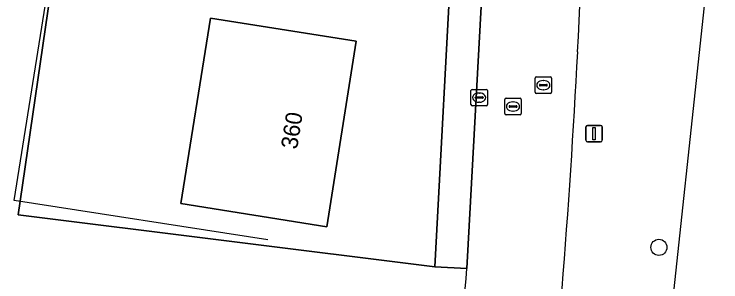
# Model space of a CAD drawing. Extents: x 154324 to 155744, y 382937 to 384188.
# Drawn here: x 155354.48 to 155397.41, y 383333.48 to 383349.73 of the extents above; entities that cross this region are included whole.
import ezdxf

# ---------------------------------------------------------------- set-up
doc = ezdxf.new("R2010")
doc.units = 0
for name, color, linetype in [('IMGEO_Berm_groen', 7, 'Continuous'), ('IMGEO_Boom', 7, 'Continuous'), ('IMGEO_Erf', 7, 'Continuous'), ('IMGEO_Groenvoorziening', 7, 'Continuous'), ('IMGEO_Hek', 7, 'Continuous'), ('IMGEO_Kolk', 7, 'Continuous'), ('IMGEO_Lichtmast', 7, 'Continuous'), ('IMGEO_Pand', 7, 'Continuous'), ('IMGEO_Pand_nummerreeks', 7, 'Continuous'), ('IMGEO_Rijbaan_lokaal_open', 7, 'Continuous'), ('IMGEO_Rioolput', 7, 'Continuous'), ('IMGEO_Voetpad_open', 7, 'Continuous')]:
    doc.layers.add(name, color=color, linetype=linetype)

msp = doc.modelspace()

# ---------------------------------------------------------------- linework, layer by layer
at = {"layer": 'IMGEO_Berm_groen'}
msp.add_lwpolyline([(155393.141, 383320.278), (155393.828, 383326.071), (155396.722, 383353.081), (155397.412, 383377.951), (155390.399, 383378.047), (155389.068, 383377.555)], dxfattribs=at)
for centre, radius, start, end in [((155026.251, 383366.771), 362.977, 356.94684, 1.70249), ((154889.758, 383373.172), 499.618, 353.74726, 357.04758)]:
    msp.add_arc(centre, radius, start, end, dxfattribs=at)
at = {"layer": 'IMGEO_Boom'}
msp.add_circle((155393.648, 383335.575), 0.489, dxfattribs=at)
at = {"layer": 'IMGEO_Erf'}
msp.add_lwpolyline([(155379.37, 383377.808), (155377.693, 383376.769), (155375.684, 383375.726), (155373.779, 383374.896), (155371.854, 383374.2), (155369.627, 383373.633), (155368.206, 383373.461), (155366.044, 383373.562), (155360.106, 383374.508), (155358.814, 383365.632), (155354.844, 383338.369), (155354.723, 383337.539), (155380.034, 383334.398), (155381.119, 383354.403)], dxfattribs=at)
msp.add_lwpolyline([(155366.404, 383349.488), (155375.255, 383348.08), (155373.484, 383336.828), (155364.602, 383338.245)], close=True, dxfattribs=at)
at = {"layer": 'IMGEO_Groenvoorziening'}
msp.add_lwpolyline([(155381.974, 383334.287), (155380.034, 383334.398), (155354.723, 383337.539), (155354.844, 383338.369), (155358.814, 383365.632)], dxfattribs=at)
msp.add_arc((155071.527, 383356.622), 311.25, 352.27674, 355.8849, dxfattribs=at)
at = {"layer": 'IMGEO_Hek'}
msp.add_lwpolyline([(155369.884, 383336.037), (155354.478, 383338.426), (155359.411, 383369.381)], dxfattribs=at)
at = {"layer": 'IMGEO_Kolk'}
for p, q in [((155382.231, 383344.237), (155382.231, 383345.089)), ((155382.306, 383345.163), (155383.158, 383345.163)), ((155382.719, 383344.943), (155382.744, 383344.943)), ((155383.232, 383345.089), (155383.232, 383344.237)), ((155382.49, 383344.657), (155382.49, 383344.669)), ((155382.928, 383344.62), (155382.53, 383344.62)), ((155382.533, 383344.706), (155382.931, 383344.706)), ((155382.974, 383344.669), (155382.974, 383344.657)), ((155383.158, 383344.163), (155382.306, 383344.163)), ((155382.742, 383344.383), (155382.717, 383344.383))]:
    msp.add_line(p, q, dxfattribs=at)
for points in [[(155382.231, 383344.237), (155382.231, 383345.089)], [(155382.306, 383345.163), (155383.158, 383345.163)], [(155383.232, 383345.089), (155383.232, 383344.237)], [(155383.158, 383344.163), (155382.306, 383344.163)]]:
    msp.add_lwpolyline(points, dxfattribs=at)
for centre, radius, start, end in [((155382.308, 383345.087), 0.0765, 91.552, 178.448), ((155382.308, 383345.087), 0.0765, 91.552, 178.448), ((155383.156, 383345.087), 0.0765, 1.552, 88.448), ((155383.156, 383345.087), 0.0765, 1.552, 88.448), ((155382.53, 383344.666), 0.0403, 85.8775, 175.7526), ((155382.527, 383344.656), 0.0366, 178.938, 274.7102), ((155382.931, 383344.663), 0.043, 264.8664, 352.4533), ((155382.935, 383344.668), 0.0386, 1.7309, 96.639), ((155382.308, 383344.239), 0.0765, 181.552, 268.448), ((155382.308, 383344.239), 0.0765, 181.552, 268.448), ((155383.156, 383344.239), 0.0765, 271.552, 358.448), ((155383.156, 383344.239), 0.0765, 271.552, 358.448)]:
    msp.add_arc(centre, radius, start, end, dxfattribs=at)
for centre, major_axis, ratio, start_param, end_param in [((155382.718, 383344.663), (-0.387, 0.002), 0.722429, 4.712389, 7.853982), ((155382.743, 383344.663), (-0.39, 0.002), 0.717154, 1.570796, 4.712389)]:
    msp.add_ellipse(centre, major_axis=major_axis, ratio=ratio, start_param=start_param, end_param=end_param, dxfattribs=at)
at = {"layer": 'IMGEO_Lichtmast'}
for p, q in [((155389.214, 383342.08), (155389.214, 383342.88)), ((155389.214, 383342.88), (155389.214, 383342.08)), ((155389.314, 383342.98), (155390.104, 383342.98)), ((155390.104, 383342.98), (155389.314, 383342.98)), ((155390.204, 383342.88), (155390.204, 383342.08)), ((155390.204, 383342.08), (155390.204, 383342.88)), ((155390.104, 383341.98), (155389.314, 383341.98)), ((155389.314, 383341.98), (155390.104, 383341.98))]:
    msp.add_line(p, q, dxfattribs=at)
msp.add_lwpolyline([(155389.634, 383342.855), (155389.784, 383342.855), (155389.784, 383342.105), (155389.634, 383342.105), (155389.634, 383342.855)], dxfattribs=at)
for centre, start, end in [((155389.314, 383342.88), 90, 180), ((155389.314, 383342.88), 90, 180), ((155390.104, 383342.88), 0, 90), ((155390.104, 383342.88), 360, 90), ((155389.314, 383342.08), 180, 270), ((155389.314, 383342.08), 180, 270), ((155390.104, 383342.08), 270, 0), ((155390.104, 383342.08), 270, 0)]:
    msp.add_arc(centre, 0.1, start, end, dxfattribs=at)
at = {"layer": 'IMGEO_Pand'}
msp.add_lwpolyline([(155375.255, 383348.08), (155366.404, 383349.488), (155364.602, 383338.245), (155373.484, 383336.828)], close=True, dxfattribs=at)
at = {"layer": 'IMGEO_Rijbaan_lokaal_open'}
msp.add_lwpolyline([(155379.61, 383421.518), (155379.69, 383421.052), (155380.297, 383417.532), (155380.555, 383416.035), (155380.615, 383415.683), (155382.189, 383397.912), (155383.12, 383377.352), (155383.264, 383374.318), (155383.19, 383366.215), (155383.081, 383354.275), (155381.974, 383334.287)], dxfattribs=at)
for centre, radius, start, end in [((155026.251, 383366.771), 362.977, 356.94684, 1.70249), ((154889.758, 383373.172), 499.618, 353.74726, 357.04758), ((155071.527, 383356.622), 311.25, 352.27674, 355.8849)]:
    msp.add_arc(centre, radius, start, end, dxfattribs=at)
at = {"layer": 'IMGEO_Rioolput'}
for p, q in [((155386.127, 383344.991), (155386.127, 383345.843)), ((155386.202, 383345.917), (155387.054, 383345.917)), ((155387.128, 383345.843), (155387.128, 383344.991)), ((155386.386, 383345.411), (155386.386, 383345.423)), ((155386.824, 383345.374), (155386.426, 383345.374)), ((155386.429, 383345.46), (155386.827, 383345.46)), ((155386.615, 383345.697), (155386.64, 383345.697)), ((155386.87, 383345.423), (155386.87, 383345.411)), ((155386.638, 383345.137), (155386.613, 383345.137)), ((155384.285, 383343.698), (155384.285, 383344.55)), ((155384.36, 383344.624), (155385.212, 383344.624)), ((155385.286, 383344.55), (155385.286, 383343.698)), ((155387.054, 383344.917), (155386.202, 383344.917)), ((155384.544, 383344.118), (155384.544, 383344.13)), ((155384.982, 383344.081), (155384.584, 383344.081)), ((155384.587, 383344.167), (155384.985, 383344.167)), ((155384.773, 383344.404), (155384.798, 383344.404)), ((155385.028, 383344.13), (155385.028, 383344.118)), ((155384.796, 383343.844), (155384.771, 383343.844)), ((155385.212, 383343.624), (155384.36, 383343.624))]:
    msp.add_line(p, q, dxfattribs=at)
for points in [[(155386.127, 383344.991), (155386.127, 383345.843)], [(155386.202, 383345.917), (155387.054, 383345.917)], [(155387.128, 383345.843), (155387.128, 383344.991)], [(155384.285, 383343.698), (155384.285, 383344.55)], [(155384.36, 383344.624), (155385.212, 383344.624)], [(155385.286, 383344.55), (155385.286, 383343.698)], [(155387.054, 383344.917), (155386.202, 383344.917)], [(155385.212, 383343.624), (155384.36, 383343.624)]]:
    msp.add_lwpolyline(points, dxfattribs=at)
for centre, radius, start, end in [((155386.204, 383345.841), 0.0765, 91.552, 178.448), ((155386.204, 383345.841), 0.0765, 91.552, 178.448), ((155387.052, 383345.841), 0.0765, 1.552, 88.448), ((155387.052, 383345.841), 0.0765, 1.552, 88.448), ((155386.426, 383345.42), 0.0403, 85.8775, 175.7526), ((155386.423, 383345.41), 0.0366, 178.938, 274.7102), ((155386.827, 383345.417), 0.043, 264.8664, 352.4533), ((155386.831, 383345.422), 0.0386, 1.7309, 96.639), ((155386.204, 383344.993), 0.0765, 181.552, 268.448), ((155386.204, 383344.993), 0.0765, 181.552, 268.448), ((155387.052, 383344.993), 0.0765, 271.552, 358.448), ((155387.052, 383344.993), 0.0765, 271.552, 358.448), ((155384.362, 383344.548), 0.0765, 91.552, 178.448), ((155384.362, 383344.548), 0.0765, 91.552, 178.448), ((155385.21, 383344.548), 0.0765, 1.552, 88.448), ((155385.21, 383344.548), 0.0765, 1.552, 88.448), ((155384.584, 383344.127), 0.0403, 85.8775, 175.7526), ((155384.581, 383344.117), 0.0366, 178.938, 274.7102), ((155384.985, 383344.124), 0.043, 264.8664, 352.4533), ((155384.989, 383344.129), 0.0386, 1.7309, 96.639), ((155384.362, 383343.7), 0.0765, 181.552, 268.448), ((155384.362, 383343.7), 0.0765, 181.552, 268.448), ((155385.21, 383343.7), 0.0765, 271.552, 358.448), ((155385.21, 383343.7), 0.0765, 271.552, 358.448)]:
    msp.add_arc(centre, radius, start, end, dxfattribs=at)
for centre, major_axis, ratio, start_param, end_param in [((155386.614, 383345.417), (-0.387, 0.002), 0.722429, 4.712389, 7.853982), ((155386.639, 383345.417), (-0.39, 0.002), 0.717154, 1.570796, 4.712389), ((155384.772, 383344.124), (-0.387, 0.002), 0.722429, 4.712389, 7.853982), ((155384.797, 383344.124), (-0.39, 0.002), 0.717154, 1.570796, 4.712389)]:
    msp.add_ellipse(centre, major_axis=major_axis, ratio=ratio, start_param=start_param, end_param=end_param, dxfattribs=at)
at = {"layer": 'IMGEO_Voetpad_open'}
msp.add_lwpolyline([(155381.184, 383376.925), (155381.295, 383374.612), (155381.119, 383354.403), (155380.034, 383334.398), (155381.974, 383334.287), (155383.081, 383354.275), (155383.19, 383366.215), (155383.264, 383374.318), (155383.12, 383377.352)], dxfattribs=at)

# ---------------------------------------------------------------- texts
at = {"layer": 'IMGEO_Pand_nummerreeks'}
msp.add_text('360', height=1, rotation=81.0531, dxfattribs=at).set_placement((155371.667, 383341.491))

doc.saveas('drawing.dxf')
